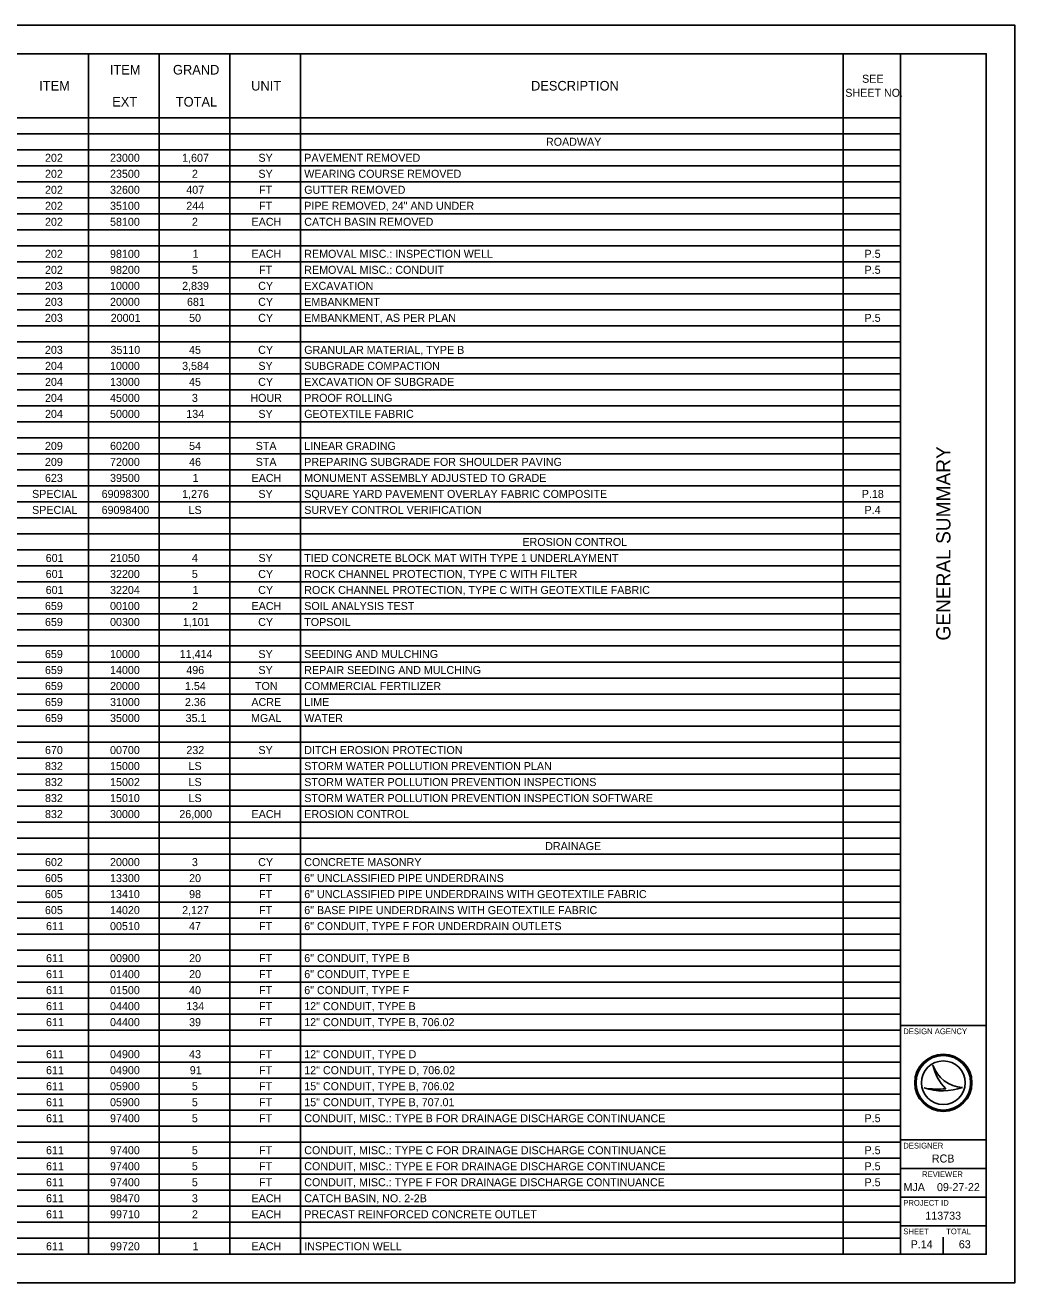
# Model space of a CAD drawing. Extents: x 0 to 34, y 0 to 22.
# Drawn here: x 16.7 to 34, y 0 to 22 of the extents above; entities that cross this region are included whole.
import ezdxf

# ---------------------------------------------------------------- set-up
doc = ezdxf.new("R2010")
doc.units = 0
for name, color, linetype in [('Default', 7, 'Continuous'), ('SH_Border', 7, 'Continuous'), ('SH_Cut_Line', 7, 'Continuous'), ('SH_Data', 7, 'Continuous')]:
    doc.layers.add(name, color=color, linetype=linetype)

msp = doc.modelspace()

# ---------------------------------------------------------------- linework, layer by layer
at = {"layer": 'Default'}
for p, q in [((1.5, 21.5), (32.004, 21.5)), ((1.5, 21.5), (32.004, 21.5)), ((17.806, 21.5), (17.806, 0.5)), ((19.041, 21.5), (19.041, 0.5)), ((20.276, 21.5), (20.276, 0.5)), ((21.512, 21.5), (21.512, 0.5)), ((30.999, 21.5), (30.999, 0.5)), ((32.004, 21.5), (32.004, 0.5)), ((32.004, 21.5), (32.004, 0.5)), ((1.5, 20.38), (32.004, 20.38)), ((1.5, 20.1), (32.004, 20.1)), ((1.5, 19.82), (32.004, 19.82)), ((1.5, 19.54), (32.004, 19.54)), ((1.5, 19.26), (32.004, 19.26)), ((1.5, 18.98), (32.004, 18.98)), ((1.5, 18.7), (32.004, 18.7)), ((1.5, 18.42), (32.004, 18.42)), ((1.5, 18.14), (32.004, 18.14)), ((1.5, 17.86), (32.004, 17.86)), ((1.5, 17.58), (32.004, 17.58)), ((1.5, 17.3), (32.004, 17.3)), ((1.5, 17.02), (32.004, 17.02)), ((1.5, 16.74), (32.004, 16.74)), ((1.5, 16.46), (32.004, 16.46)), ((1.5, 16.18), (32.004, 16.18)), ((1.5, 15.9), (32.004, 15.9)), ((1.5, 15.62), (32.004, 15.62)), ((1.5, 15.34), (32.004, 15.34)), ((1.5, 15.06), (32.004, 15.06)), ((1.5, 14.78), (32.004, 14.78)), ((1.5, 14.5), (32.004, 14.5)), ((1.5, 14.22), (32.004, 14.22)), ((1.5, 13.94), (32.004, 13.94)), ((1.5, 13.66), (32.004, 13.66)), ((1.5, 13.38), (32.004, 13.38)), ((1.5, 13.1), (32.004, 13.1)), ((1.5, 12.82), (32.004, 12.82)), ((1.5, 12.54), (32.004, 12.54)), ((1.5, 12.26), (32.004, 12.26)), ((1.5, 11.98), (32.004, 11.98)), ((1.5, 11.7), (32.004, 11.7)), ((1.5, 11.42), (32.004, 11.42)), ((1.5, 11.14), (32.004, 11.14)), ((1.5, 10.86), (32.004, 10.86)), ((1.5, 10.58), (32.004, 10.58)), ((1.5, 10.3), (32.004, 10.3)), ((1.5, 10.02), (32.004, 10.02)), ((1.5, 9.74), (32.004, 9.74)), ((1.5, 9.46), (32.004, 9.46)), ((1.5, 9.18), (32.004, 9.18)), ((1.5, 8.9), (32.004, 8.9)), ((1.5, 8.62), (32.004, 8.62)), ((1.5, 8.34), (32.004, 8.34)), ((1.5, 8.06), (32.004, 8.06)), ((1.5, 7.78), (32.004, 7.78)), ((1.5, 7.5), (32.004, 7.5)), ((1.5, 7.22), (32.004, 7.22)), ((1.5, 6.94), (32.004, 6.94)), ((1.5, 6.66), (32.004, 6.66)), ((1.5, 6.38), (32.004, 6.38)), ((1.5, 6.1), (32.004, 6.1)), ((1.5, 5.82), (32.004, 5.82)), ((1.5, 5.54), (32.004, 5.54)), ((1.5, 5.26), (32.004, 5.26)), ((1.5, 4.98), (32.004, 4.98)), ((1.5, 4.7), (32.004, 4.7)), ((1.5, 4.42), (32.004, 4.42)), ((1.5, 4.14), (32.004, 4.14)), ((1.5, 3.86), (32.004, 3.86)), ((1.5, 3.58), (32.004, 3.58)), ((1.5, 3.3), (32.004, 3.3)), ((1.5, 3.02), (32.004, 3.02)), ((1.5, 2.74), (32.004, 2.74)), ((1.5, 2.46), (32.004, 2.46)), ((1.5, 2.18), (32.004, 2.18)), ((1.5, 1.9), (32.004, 1.9)), ((1.5, 1.62), (32.004, 1.62)), ((1.5, 1.34), (32.004, 1.34)), ((1.5, 1.06), (32.004, 1.06)), ((1.5, 0.78), (32.004, 0.78)), ((1.5, 0.5), (32.004, 0.5)), ((1.5, 0.5), (32.004, 0.5))]:
    msp.add_line(p, q, dxfattribs=at)
at = {"layer": 'SH_Border'}
for p, q in [((32, 0.5), (32, 21.5)), ((32, 4.5), (33.5, 4.5)), ((32, 2.5), (33.5, 2.5)), ((32, 2), (33.5, 2)), ((32, 1.5), (33.5, 1.5)), ((32, 1), (33.5, 1))]:
    msp.add_line(p, q, dxfattribs=at)
msp.add_lwpolyline([(1.5, 21.5), (33.5, 21.5), (33.5, 0.5), (1.5, 0.5)], close=True, dxfattribs=at)
at = {"layer": 'SH_Cut_Line'}
msp.add_lwpolyline([(0, 0), (34, 0), (34, 22), (0, 22)], close=True, dxfattribs=at)
at = {"layer": 'SH_Data'}
for p, q in [((32.567, 3.81), (32.567, 3.81)), ((32.417, 3.41), (32.417, 3.41)), ((32.75, 3.5), (32.75, 3.5)), ((33.087, 3.419), (33.087, 3.419)), ((32.375, 0.675), (32.375, 0.675)), ((32.75, 0.5), (32.75, 0.8))]:
    msp.add_line(p, q, dxfattribs=at)
for radius in [0.5, 0.477, 0.477, 0.382]:
    msp.add_circle((32.75, 3.5), radius, dxfattribs=at)
for centre, radius, start, end in [((33.116, 3.998), 0.58, 198.9257, 198.9319), ((33.347, 3.97), 0.796, 191.6379, 191.6421), ((33.116, 3.998), 0.58, 198.9319, 267.1657), ((33.347, 3.97), 0.796, 191.6421, 226.0947), ((32.739, 4.37), 1.013, 251.4576, 290.0832), ((32.648, 4.654), 1.266, 259.4964, 259.4995), ((32.739, 4.37), 1.013, 251.4527, 251.4576), ((32.648, 4.654), 1.266, 259.4995, 276.6672)]:
    msp.add_arc(centre, radius, start, end, dxfattribs=at)

# ---------------------------------------------------------------- texts
at = {"layer": 'Default'}
for s, height, p in [('ITEM', 0.168, (18.179, 21.136)), ('GRAND', 0.168, (19.283, 21.136)), ('SEE ', 0.14, (31.33, 20.992)), ('ITEM', 0.168, (16.944, 20.856)), ('UNIT', 0.168, (20.65, 20.856)), ('DESCRIPTION', 0.168, (25.542, 20.856)), ('EXT', 0.168, (18.22, 20.576)), ('TOTAL', 0.168, (19.332, 20.576)), ('SHEET NO.', 0.14, (31.036, 20.747)), ('ROADWAY', 0.14, (25.804, 19.89)), ('202', 0.14, (17.046, 19.61)), ('23000', 0.14, (18.183, 19.61)), ('1,607', 0.14, (19.443, 19.61)), ('SY', 0.14, (20.777, 19.61)), ('PAVEMENT REMOVED', 0.14, (21.578, 19.61)), ('202', 0.14, (17.046, 19.33)), ('23500', 0.14, (18.183, 19.33)), ('2', 0.14, (19.615, 19.33)), ('SY', 0.14, (20.777, 19.33)), ('WEARING COURSE REMOVED', 0.14, (21.578, 19.33)), ('202', 0.14, (17.046, 19.05)), ('32600', 0.14, (18.183, 19.05)), ('407', 0.14, (19.516, 19.05)), ('FT', 0.14, (20.788, 19.05)), ('GUTTER REMOVED', 0.14, (21.578, 19.05)), ('202', 0.14, (17.046, 18.77)), ('35100', 0.14, (18.183, 18.77)), ('244', 0.14, (19.516, 18.77)), ('FT', 0.14, (20.788, 18.77)), ('PIPE REMOVED, 24" AND UNDER', 0.14, (21.578, 18.77)), ('202', 0.14, (17.046, 18.49)), ('58100', 0.14, (18.183, 18.49)), ('2', 0.14, (19.615, 18.49)), ('EACH', 0.14, (20.657, 18.49)), ('CATCH BASIN REMOVED', 0.14, (21.578, 18.49)), ('202', 0.14, (17.046, 17.93)), ('98100', 0.14, (18.183, 17.93)), ('1', 0.14, (19.626, 17.93)), ('EACH', 0.14, (20.657, 17.93)), ('REMOVAL MISC.: INSPECTION WELL', 0.14, (21.578, 17.93)), ('P.5', 0.14, (31.373, 17.93)), ('202', 0.14, (17.046, 17.65)), ('98200', 0.14, (18.183, 17.65)), ('5', 0.14, (19.613, 17.65)), ('FT', 0.14, (20.788, 17.65)), ('REMOVAL MISC.: CONDUIT', 0.14, (21.578, 17.65)), ('P.5', 0.14, (31.373, 17.65)), ('203', 0.14, (17.045, 17.37)), ('10000', 0.14, (18.183, 17.37)), ('2,839', 0.14, (19.443, 17.37)), ('CY', 0.14, (20.773, 17.37)), ('EXCAVATION', 0.14, (21.578, 17.37)), ('203', 0.14, (17.045, 17.09)), ('20000', 0.14, (18.183, 17.09)), ('681', 0.14, (19.528, 17.09)), ('CY', 0.14, (20.773, 17.09)), ('EMBANKMENT', 0.14, (21.578, 17.09)), ('203', 0.14, (17.045, 16.81)), ('20001', 0.14, (18.195, 16.81)), ('50', 0.14, (19.565, 16.81)), ('CY', 0.14, (20.773, 16.81)), ('EMBANKMENT, AS PER PLAN', 0.14, (21.578, 16.81)), ('P.5', 0.14, (31.373, 16.81)), ('203', 0.14, (17.045, 16.25)), ('35110', 0.14, (18.19, 16.25)), ('45', 0.14, (19.564, 16.25)), ('CY', 0.14, (20.773, 16.25)), ('GRANULAR MATERIAL, TYPE B', 0.14, (21.578, 16.25)), ('204', 0.14, (17.046, 15.97)), ('10000', 0.14, (18.183, 15.97)), ('3,584', 0.14, (19.443, 15.97)), ('SY', 0.14, (20.777, 15.97)), ('SUBGRADE COMPACTION', 0.14, (21.578, 15.97)), ('204', 0.14, (17.046, 15.69)), ('13000', 0.14, (18.183, 15.69)), ('45', 0.14, (19.564, 15.69)), ('CY', 0.14, (20.773, 15.69)), ('EXCAVATION OF SUBGRADE', 0.14, (21.578, 15.69)), ('204', 0.14, (17.046, 15.41)), ('45000', 0.14, (18.183, 15.41)), ('3', 0.14, (19.614, 15.41)), ('HOUR', 0.14, (20.636, 15.41)), ('PROOF ROLLING', 0.14, (21.578, 15.41)), ('204', 0.14, (17.046, 15.13)), ('50000', 0.14, (18.183, 15.13)), ('134', 0.14, (19.516, 15.13)), ('SY', 0.14, (20.777, 15.13)), ('GEOTEXTILE FABRIC', 0.14, (21.578, 15.13)), ('209', 0.14, (17.045, 14.57)), ('60200', 0.14, (18.183, 14.57)), ('54', 0.14, (19.565, 14.57)), ('STA', 0.14, (20.729, 14.57)), ('LINEAR GRADING', 0.14, (21.578, 14.57)), ('209', 0.14, (17.045, 14.29)), ('72000', 0.14, (18.183, 14.29)), ('46', 0.14, (19.565, 14.29)), ('STA', 0.14, (20.729, 14.29)), ('PREPARING SUBGRADE FOR SHOULDER PAVING', 0.14, (21.578, 14.29)), ('623', 0.14, (17.045, 14.01)), ('39500', 0.14, (18.183, 14.01)), ('1', 0.14, (19.626, 14.01)), ('EACH', 0.14, (20.657, 14.01)), ('MONUMENT ASSEMBLY ADJUSTED TO GRADE', 0.14, (21.578, 14.01)), ('SPECIAL', 0.14, (16.82, 13.73)), ('69098300', 0.14, (18.036, 13.73)), ('1,276', 0.14, (19.443, 13.73)), ('SY', 0.14, (20.777, 13.73)), ('SQUARE YARD PAVEMENT OVERLAY FABRIC COMPOSITE', 0.14, (21.578, 13.73)), ('P.18', 0.14, (31.324, 13.73)), ('SPECIAL', 0.14, (16.82, 13.45)), ('69098400', 0.14, (18.036, 13.45)), ('LS', 0.14, (19.556, 13.45)), ('SURVEY CONTROL VERIFICATION', 0.14, (21.578, 13.45)), ('P.4', 0.14, (31.373, 13.45)), ('EROSION CONTROL', 0.14, (25.392, 12.89)), ('601', 0.14, (17.058, 12.61)), ('21050', 0.14, (18.183, 12.61)), ('4', 0.14, (19.614, 12.61)), ('SY', 0.14, (20.777, 12.61)), ('TIED CONCRETE BLOCK MAT WITH TYPE 1 UNDERLAYMENT', 0.14, (21.578, 12.61)), ('601', 0.14, (17.058, 12.33)), ('32200', 0.14, (18.183, 12.33)), ('5', 0.14, (19.613, 12.33)), ('CY', 0.14, (20.773, 12.33)), ('ROCK CHANNEL PROTECTION, TYPE C WITH FILTER', 0.14, (21.578, 12.33)), ('601', 0.14, (17.058, 12.05)), ('32204', 0.14, (18.183, 12.05)), ('1', 0.14, (19.626, 12.05)), ('CY', 0.14, (20.773, 12.05)), ('ROCK CHANNEL PROTECTION, TYPE C WITH GEOTEXTILE FABRIC', 0.14, (21.578, 12.05)), ('659', 0.14, (17.045, 11.77)), ('00100', 0.14, (18.183, 11.77)), ('2', 0.14, (19.615, 11.77)), ('EACH', 0.14, (20.657, 11.77)), ('SOIL ANALYSIS TEST', 0.14, (21.578, 11.77)), ('659', 0.14, (17.045, 11.49)), ('00300', 0.14, (18.183, 11.49)), ('1,101', 0.14, (19.455, 11.49)), ('CY', 0.14, (20.773, 11.49)), ('TOPSOIL', 0.14, (21.578, 11.49)), ('659', 0.14, (17.045, 10.93)), ('10000', 0.14, (18.183, 10.93)), ('11,414', 0.14, (19.401, 10.93)), ('SY', 0.14, (20.777, 10.93)), ('SEEDING AND MULCHING', 0.14, (21.578, 10.93)), ('659', 0.14, (17.045, 10.65)), ('14000', 0.14, (18.183, 10.65)), ('496', 0.14, (19.516, 10.65)), ('SY', 0.14, (20.777, 10.65)), ('REPAIR SEEDING AND MULCHING', 0.14, (21.578, 10.65)), ('659', 0.14, (17.045, 10.37)), ('20000', 0.14, (18.183, 10.37)), ('1.54', 0.14, (19.492, 10.37)), ('TON', 0.14, (20.717, 10.37)), ('COMMERCIAL FERTILIZER', 0.14, (21.578, 10.37)), ('659', 0.14, (17.045, 10.09)), ('31000', 0.14, (18.183, 10.09)), ('2.36', 0.14, (19.492, 10.09)), ('ACRE', 0.14, (20.654, 10.09)), ('LIME', 0.14, (21.578, 10.09)), ('659', 0.14, (17.045, 9.81)), ('35000', 0.14, (18.183, 9.81)), ('35.1', 0.14, (19.504, 9.81)), ('MGAL', 0.14, (20.648, 9.81)), ('WATER', 0.14, (21.578, 9.81)), ('670', 0.14, (17.046, 9.25)), ('00700', 0.14, (18.183, 9.25)), ('232', 0.14, (19.517, 9.25)), ('SY', 0.14, (20.777, 9.25)), ('DITCH EROSION PROTECTION', 0.14, (21.578, 9.25)), ('832', 0.14, (17.046, 8.97)), ('15000', 0.14, (18.183, 8.97)), ('LS', 0.14, (19.556, 8.97)), ('STORM WATER POLLUTION PREVENTION PLAN', 0.14, (21.578, 8.97)), ('832', 0.14, (17.046, 8.69)), ('15002', 0.14, (18.184, 8.69)), ('LS', 0.14, (19.556, 8.69)), ('STORM WATER POLLUTION PREVENTION INSPECTIONS', 0.14, (21.578, 8.69)), ('832', 0.14, (17.046, 8.41)), ('15010', 0.14, (18.183, 8.41)), ('LS', 0.14, (19.556, 8.41)), ('STORM WATER POLLUTION PREVENTION INSPECTION SOFTWARE', 0.14, (21.578, 8.41)), ('832', 0.14, (17.046, 8.13)), ('30000', 0.14, (18.183, 8.13)), ('26,000', 0.14, (19.394, 8.13)), ('EACH', 0.14, (20.657, 8.13)), ('EROSION CONTROL', 0.14, (21.578, 8.13)), ('DRAINAGE', 0.14, (25.79, 7.57)), ('602', 0.14, (17.046, 7.29)), ('20000', 0.14, (18.183, 7.29)), ('3', 0.14, (19.614, 7.29)), ('CY', 0.14, (20.773, 7.29)), ('CONCRETE MASONRY', 0.14, (21.578, 7.29)), ('605', 0.14, (17.045, 7.01)), ('13300', 0.14, (18.183, 7.01)), ('20', 0.14, (19.565, 7.01)), ('FT', 0.14, (20.788, 7.01)), ('6" UNCLASSIFIED PIPE UNDERDRAINS', 0.14, (21.578, 7.01)), ('605', 0.14, (17.045, 6.73)), ('13410', 0.14, (18.183, 6.73)), ('98', 0.14, (19.565, 6.73)), ('FT', 0.14, (20.788, 6.73)), ('6" UNCLASSIFIED PIPE UNDERDRAINS WITH GEOTEXTILE FABRIC', 0.14, (21.578, 6.73)), ('605', 0.14, (17.045, 6.45)), ('14020', 0.14, (18.183, 6.45)), ('2,127', 0.14, (19.443, 6.45)), ('FT', 0.14, (20.788, 6.45)), ('6" BASE PIPE UNDERDRAINS WITH GEOTEXTILE FABRIC', 0.14, (21.578, 6.45)), ('611', 0.14, (17.064, 6.17)), ('00510', 0.14, (18.183, 6.17)), ('47', 0.14, (19.565, 6.17)), ('FT', 0.14, (20.788, 6.17)), ('6" CONDUIT, TYPE F FOR UNDERDRAIN OUTLETS', 0.14, (21.578, 6.17)), ('611', 0.14, (17.064, 5.61)), ('00900', 0.14, (18.183, 5.61)), ('20', 0.14, (19.565, 5.61)), ('FT', 0.14, (20.788, 5.61)), ('6" CONDUIT, TYPE B', 0.14, (21.578, 5.61)), ('611', 0.14, (17.064, 5.33)), ('01400', 0.14, (18.183, 5.33)), ('20', 0.14, (19.565, 5.33)), ('FT', 0.14, (20.788, 5.33)), ('6" CONDUIT, TYPE E', 0.14, (21.578, 5.33)), ('611', 0.14, (17.064, 5.05)), ('01500', 0.14, (18.183, 5.05)), ('40', 0.14, (19.565, 5.05)), ('FT', 0.14, (20.788, 5.05)), ('6" CONDUIT, TYPE F', 0.14, (21.578, 5.05)), ('611', 0.14, (17.064, 4.77)), ('04400', 0.14, (18.183, 4.77)), ('134', 0.14, (19.516, 4.77)), ('FT', 0.14, (20.788, 4.77)), ('12" CONDUIT, TYPE B', 0.14, (21.578, 4.77)), ('611', 0.14, (17.064, 4.49)), ('04400', 0.14, (18.183, 4.49)), ('39', 0.14, (19.565, 4.49)), ('FT', 0.14, (20.788, 4.49)), ('12" CONDUIT, TYPE B, 706.02', 0.14, (21.578, 4.49)), ('611', 0.14, (17.064, 3.93)), ('04900', 0.14, (18.183, 3.93)), ('43', 0.14, (19.565, 3.93)), ('FT', 0.14, (20.788, 3.93)), ('12" CONDUIT, TYPE D', 0.14, (21.578, 3.93)), ('611', 0.14, (17.064, 3.65)), ('04900', 0.14, (18.183, 3.65)), ('91', 0.14, (19.577, 3.65)), ('FT', 0.14, (20.788, 3.65)), ('12" CONDUIT, TYPE D, 706.02', 0.14, (21.578, 3.65)), ('611', 0.14, (17.064, 3.37)), ('05900', 0.14, (18.183, 3.37)), ('5', 0.14, (19.613, 3.37)), ('FT', 0.14, (20.788, 3.37)), ('15" CONDUIT, TYPE B, 706.02', 0.14, (21.578, 3.37)), ('611', 0.14, (17.064, 3.09)), ('05900', 0.14, (18.183, 3.09)), ('5', 0.14, (19.613, 3.09)), ('FT', 0.14, (20.788, 3.09)), ('15" CONDUIT, TYPE B, 707.01', 0.14, (21.578, 3.09)), ('611', 0.14, (17.064, 2.81)), ('97400', 0.14, (18.183, 2.81)), ('5', 0.14, (19.613, 2.81)), ('FT', 0.14, (20.788, 2.81)), ('CONDUIT, MISC.: TYPE B FOR DRAINAGE DISCHARGE CONTINUANCE', 0.14, (21.578, 2.81)), ('P.5', 0.14, (31.373, 2.81)), ('611', 0.14, (17.064, 2.25)), ('97400', 0.14, (18.183, 2.25)), ('5', 0.14, (19.613, 2.25)), ('FT', 0.14, (20.788, 2.25)), ('CONDUIT, MISC.: TYPE C FOR DRAINAGE DISCHARGE CONTINUANCE', 0.14, (21.578, 2.25)), ('P.5', 0.14, (31.373, 2.25)), ('611', 0.14, (17.064, 1.97)), ('97400', 0.14, (18.183, 1.97)), ('5', 0.14, (19.613, 1.97)), ('FT', 0.14, (20.788, 1.97)), ('CONDUIT, MISC.: TYPE E FOR DRAINAGE DISCHARGE CONTINUANCE', 0.14, (21.578, 1.97)), ('P.5', 0.14, (31.373, 1.97)), ('611', 0.14, (17.064, 1.69)), ('97400', 0.14, (18.183, 1.69)), ('5', 0.14, (19.613, 1.69)), ('FT', 0.14, (20.788, 1.69)), ('CONDUIT, MISC.: TYPE F FOR DRAINAGE DISCHARGE CONTINUANCE', 0.14, (21.578, 1.69)), ('P.5', 0.14, (31.373, 1.69)), ('611', 0.14, (17.064, 1.41)), ('98470', 0.14, (18.183, 1.41)), ('3', 0.14, (19.614, 1.41)), ('EACH', 0.14, (20.657, 1.41)), ('CATCH BASIN, NO. 2-2B', 0.14, (21.578, 1.41)), ('611', 0.14, (17.064, 1.13)), ('99710', 0.14, (18.183, 1.13)), ('2', 0.14, (19.615, 1.13)), ('EACH', 0.14, (20.657, 1.13)), ('PRECAST REINFORCED CONCRETE OUTLET', 0.14, (21.578, 1.13)), ('611', 0.14, (17.064, 0.57)), ('99720', 0.14, (18.183, 0.57)), ('1', 0.14, (19.626, 0.57)), ('EACH', 0.14, (20.657, 0.57)), ('INSPECTION WELL', 0.14, (21.578, 0.57))]:
    msp.add_text(s, height=height, dxfattribs=at).set_placement(p)
at = {"layer": 'SH_Data'}
msp.add_text('GENERAL SUMMARY', height=0.25, rotation=90, dxfattribs=at).set_placement((32.875, 11.235))
for s, height, p in [('DESIGN AGENCY', 0.1, (32.05, 4.35)), ('DESIGNER', 0.1, (32.05, 2.35)), ('RCB', 0.14, (32.549, 2.105)), ('REVIEWER', 0.1, (32.378, 1.85)), ('MJA', 0.14, (32.054, 1.605)), ('09-27-22', 0.14, (32.639, 1.605)), ('PROJECT ID', 0.1, (32.05, 1.35)), ('113733', 0.14, (32.435, 1.105)), ('SHEET', 0.1, (32.05, 0.85)), ('TOTAL', 0.1, (32.8, 0.85)), ('P.14', 0.14, (32.179, 0.605)), ('63', 0.14, (33.021, 0.605))]:
    msp.add_text(s, height=height, dxfattribs=at).set_placement(p)

doc.saveas('drawing.dxf')
